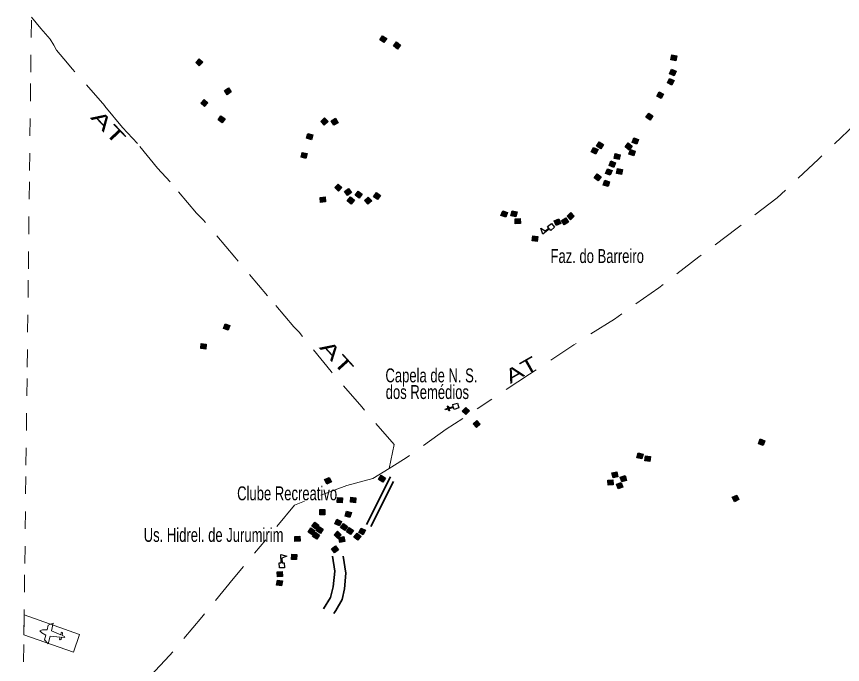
# Model space of a CAD drawing. Extents: x 679 to 705, y 7427.4 to 7455.4.
# Drawn here: x 679.037 to 683.784, y 7431.066 to 7434.793 of the extents above; entities that cross this region are included whole.
import ezdxf
from ezdxf.enums import TextEntityAlignment as Align

# ---------------------------------------------------------------- set-up
doc = ezdxf.new("R2010")
doc.units = 0
doc.header["$LTSCALE"] = 0.032
doc.linetypes.add('DOT_DASHED', pattern=[7.7, 5, -1.2, 0.3, -1.2])
doc.linetypes.add('SHORT_DASHED', pattern=[2.7, 1.5, -1.2])
for name, color, linetype, lineweight in [('18', 7, 'Continuous', 13), ('2', 7, 'Continuous', 25), ('26', 7, 'Continuous', 35), ('4', 7, 'Continuous', 25), ('56', 7, 'DOT_DASHED', 13), ('58', 7, 'SHORT_DASHED', 13), ('6', 7, 'Continuous', 25)]:
    doc.layers.add(name, color=color, linetype=linetype, lineweight=lineweight)
doc.layers.add('61', color=7, linetype='Continuous')

msp = doc.modelspace()

# ---------------------------------------------------------------- hatches: boundary and pattern name
at = {"layer": '2'}
for points in [[(681.1398, 7434.6824), (681.1644, 7434.6671), (681.149, 7434.6425), (681.1244, 7434.6578)], [(681.2217, 7434.6462), (681.2447, 7434.6286), (681.2272, 7434.6056), (681.2041, 7434.6232)], [(682.832, 7434.5663), (682.8263, 7434.5379), (682.7979, 7434.5436), (682.8036, 7434.572)], [(680.0872, 7434.5494), (680.108, 7434.5292), (680.0878, 7434.5084), (680.067, 7434.5286)], [(682.8016, 7434.4889), (682.8283, 7434.4774), (682.8167, 7434.4508), (682.7901, 7434.4623)], [(682.7891, 7434.4369), (682.8157, 7434.4252), (682.8039, 7434.3987), (682.7774, 7434.4104)], [(680.256, 7434.3831), (680.2717, 7434.3588), (680.2473, 7434.3431), (680.2316, 7434.3674)], [(682.7301, 7434.3601), (682.7557, 7434.3464), (682.7419, 7434.3209), (682.7164, 7434.3346)], [(680.116, 7434.316), (680.1375, 7434.2966), (680.1181, 7434.275), (680.0966, 7434.2945)], [(682.6701, 7434.2369), (682.6942, 7434.2207), (682.6781, 7434.1966), (682.654, 7434.2128)], [(680.2117, 7434.2214), (680.2357, 7434.2051), (680.2194, 7434.1812), (680.1954, 7434.1975)], [(680.8077, 7434.2092), (680.8274, 7434.1879), (680.8061, 7434.1682), (680.7864, 7434.1895)], [(680.8712, 7434.2071), (680.8854, 7434.1819), (680.8601, 7434.1676), (680.8459, 7434.1929)], [(680.7399, 7434.1121), (680.7321, 7434.0842), (680.7042, 7434.092), (680.712, 7434.1199)], [(682.5842, 7434.0958), (682.6116, 7434.0861), (682.6018, 7434.0588), (682.5745, 7434.0685)], [(682.3857, 7434.0719), (682.4104, 7434.0567), (682.3952, 7434.032), (682.3705, 7434.0473)], [(682.5521, 7434.0653), (682.5751, 7434.0475), (682.5573, 7434.0246), (682.5344, 7434.0424)], [(680.7073, 7434.0044), (680.7004, 7433.9762), (680.6722, 7433.9831), (680.6791, 7434.0113)], [(682.3792, 7434.0274), (682.3665, 7434.0013), (682.3404, 7434.014), (682.3531, 7434.0401)], [(682.5063, 7433.9979), (682.5003, 7433.9695), (682.472, 7433.9755), (682.4779, 7434.0039)], [(682.5656, 7434.0282), (682.5931, 7434.019), (682.584, 7433.9915), (682.5565, 7434.0007)], [(682.4798, 7433.9514), (682.4691, 7433.9244), (682.4421, 7433.9352), (682.4529, 7433.9621)], [(682.433, 7433.9175), (682.46, 7433.907), (682.4495, 7433.88), (682.4225, 7433.8905)], [(682.5187, 7433.9125), (682.5134, 7433.884), (682.4849, 7433.8893), (682.4902, 7433.9178)], [(682.3732, 7433.8881), (682.3966, 7433.8709), (682.3794, 7433.8475), (682.356, 7433.8647)], [(682.4181, 7433.851), (682.4456, 7433.8418), (682.4364, 7433.8143), (682.4089, 7433.8235)], [(680.8862, 7433.8293), (680.9071, 7433.8093), (680.8871, 7433.7883), (680.8661, 7433.8083)], [(680.9455, 7433.8038), (680.963, 7433.7807), (680.9399, 7433.7632), (680.9224, 7433.7863)], [(680.9998, 7433.7881), (681.0236, 7433.7716), (681.0071, 7433.7478), (680.9833, 7433.7643)], [(681.1051, 7433.7797), (681.129, 7433.7633), (681.1126, 7433.7394), (681.0887, 7433.7558)], [(680.8105, 7433.7547), (680.8132, 7433.7259), (680.7844, 7433.7231), (680.7816, 7433.752)], [(680.9561, 7433.7546), (680.9788, 7433.7366), (680.9607, 7433.7139), (680.938, 7433.7319)], [(681.059, 7433.7534), (681.0785, 7433.7318), (681.057, 7433.7124), (681.0375, 7433.7339)], [(681.8586, 7433.6648), (681.8482, 7433.6377), (681.8212, 7433.6481), (681.8316, 7433.6752)], [(681.9136, 7433.6685), (681.9069, 7433.6403), (681.8787, 7433.647), (681.8854, 7433.6752)], [(682.2222, 7433.6648), (682.242, 7433.6436), (682.2208, 7433.6238), (682.201, 7433.645)], [(681.9312, 7433.6304), (681.9325, 7433.6014), (681.9035, 7433.6001), (681.9022, 7433.6291)], [(682.1545, 7433.6283), (682.1656, 7433.6015), (682.1389, 7433.5904), (682.1277, 7433.6171)], [(682.1937, 7433.6348), (682.209, 7433.6102), (682.1843, 7433.5949), (682.169, 7433.6196)], [(682.0334, 7433.5279), (682.0293, 7433.4992), (682.0006, 7433.5033), (682.0047, 7433.532)], [(680.2631, 7433.0156), (680.2539, 7432.9881), (680.2264, 7432.9973), (680.2356, 7433.0248)], [(680.1278, 7432.9082), (680.1245, 7432.8794), (680.0957, 7432.8826), (680.099, 7432.9114)], [(681.6188, 7432.5439), (681.6397, 7432.5238), (681.6197, 7432.5029), (681.5987, 7432.523)], [(681.6816, 7432.4694), (681.7015, 7432.4483), (681.6804, 7432.4284), (681.6605, 7432.4495)], [(683.3378, 7432.353), (683.3278, 7432.3258), (683.3006, 7432.3358), (683.3106, 7432.363)], [(682.638, 7432.2759), (682.6306, 7432.2478), (682.6026, 7432.2552), (682.61, 7432.2833)], [(682.6798, 7432.2629), (682.6769, 7432.234), (682.6481, 7432.2369), (682.6509, 7432.2658)], [(680.8342, 7432.1422), (680.8465, 7432.1159), (680.8202, 7432.1036), (680.8079, 7432.1299)], [(681.1579, 7432.1379), (681.1419, 7432.1137), (681.1177, 7432.1296), (681.1336, 7432.1538)], [(682.4867, 7432.1742), (682.4932, 7432.1459), (682.465, 7432.1394), (682.4585, 7432.1677)], [(682.5346, 7432.1524), (682.5433, 7432.1248), (682.5156, 7432.1161), (682.5069, 7432.1437)], [(682.4637, 7432.1276), (682.4661, 7432.0987), (682.4372, 7432.0963), (682.4348, 7432.1252)], [(682.5115, 7432.1133), (682.5211, 7432.086), (682.4938, 7432.0764), (682.4842, 7432.1037)], [(680.9113, 7432.0241), (680.9095, 7431.9952), (680.8805, 7431.997), (680.8824, 7432.026)], [(680.9876, 7432.0251), (680.9849, 7431.9962), (680.956, 7431.9989), (680.9587, 7432.0278)], [(683.1766, 7432.0406), (683.1888, 7432.0143), (683.1625, 7432.0021), (683.1503, 7432.0284)], [(680.7797, 7431.9563), (680.8087, 7431.9563), (680.8087, 7431.9273), (680.7797, 7431.9273)], [(680.9615, 7431.9392), (680.9536, 7431.9113), (680.9257, 7431.9193), (680.9337, 7431.9472)], [(680.7522, 7431.884), (680.7752, 7431.8665), (680.7577, 7431.8434), (680.7346, 7431.861)], [(680.7763, 7431.8599), (680.8004, 7431.8438), (680.7843, 7431.8197), (680.7602, 7431.8358)], [(680.9052, 7431.8888), (680.8932, 7431.8624), (680.8668, 7431.8744), (680.8788, 7431.9008)], [(680.9399, 7431.8602), (680.9234, 7431.8363), (680.8995, 7431.8528), (680.916, 7431.8767)], [(680.728, 7431.8514), (680.7525, 7431.8359), (680.7371, 7431.8114), (680.7125, 7431.8268)], [(680.7552, 7431.8262), (680.7793, 7431.8101), (680.7632, 7431.786), (680.7391, 7431.8021)], [(680.9037, 7431.8124), (680.8839, 7431.7912), (680.8627, 7431.8109), (680.8824, 7431.8322)], [(680.9497, 7431.853), (680.9733, 7431.8362), (680.9564, 7431.8126), (680.9328, 7431.8294)], [(681.0173, 7431.8028), (680.9994, 7431.78), (680.9766, 7431.7979), (680.9946, 7431.8207)], [(681.0431, 7431.8375), (681.0302, 7431.8116), (681.0042, 7431.8246), (681.0172, 7431.8505)], [(680.6655, 7431.8033), (680.6665, 7431.7743), (680.6375, 7431.7733), (680.6365, 7431.8023)], [(680.9188, 7431.801), (680.9243, 7431.7725), (680.8959, 7431.767), (680.8903, 7431.7954)], [(680.8699, 7431.7491), (680.8873, 7431.7259), (680.8641, 7431.7085), (680.8467, 7431.7317)], [(680.6483, 7431.6982), (680.647, 7431.6692), (680.618, 7431.6705), (680.6193, 7431.6995)], [(680.5641, 7431.6011), (680.5655, 7431.5721), (680.5366, 7431.5706), (680.5351, 7431.5996)], [(680.5655, 7431.546), (680.5607, 7431.5174), (680.5321, 7431.5221), (680.5369, 7431.5507)]]:
    msp.add_hatch(color=256, dxfattribs=at).paths.add_polyline_path(points)

# ---------------------------------------------------------------- linework, layer by layer
at = {"layer": '18'}
for points in [[(679.0801, 7431.236), (679.0814, 7431.3513), (679.3998, 7431.2391), (679.3656, 7431.1374)], [(679.1712, 7431.2599), (679.1874, 7431.2644), (679.2134, 7431.266), (679.2201, 7431.2924), (679.2487, 7431.3044), (679.2377, 7431.2598), (679.2914, 7431.2371), (679.2942, 7431.2487), (679.2993, 7431.2515), (679.3023, 7431.2466), (679.299, 7431.2334), (679.3122, 7431.2275), (679.3156, 7431.2235), (679.3107, 7431.2214), (679.2964, 7431.2228), (679.2933, 7431.2097), (679.2881, 7431.2067), (679.2851, 7431.2118), (679.2877, 7431.2229), (679.2298, 7431.2285), (679.2186, 7431.184), (679.1989, 7431.208), (679.2056, 7431.2345), (679.1833, 7431.2482)]]:
    msp.add_lwpolyline(points, close=True, dxfattribs=at)
at = {"layer": '2'}
for points in [[(681.1398, 7434.6824), (681.1644, 7434.6671), (681.149, 7434.6425), (681.1244, 7434.6578)], [(681.2217, 7434.6462), (681.2447, 7434.6286), (681.2272, 7434.6056), (681.2041, 7434.6232)], [(682.832, 7434.5663), (682.8263, 7434.5379), (682.7979, 7434.5436), (682.8036, 7434.572)], [(680.0872, 7434.5494), (680.108, 7434.5292), (680.0878, 7434.5084), (680.067, 7434.5286)], [(682.8016, 7434.4889), (682.8283, 7434.4774), (682.8167, 7434.4508), (682.7901, 7434.4623)], [(682.7891, 7434.4369), (682.8157, 7434.4252), (682.8039, 7434.3987), (682.7774, 7434.4104)], [(680.256, 7434.3831), (680.2717, 7434.3588), (680.2473, 7434.3431), (680.2316, 7434.3674)], [(682.7301, 7434.3601), (682.7557, 7434.3464), (682.7419, 7434.3209), (682.7164, 7434.3346)], [(680.116, 7434.316), (680.1375, 7434.2966), (680.1181, 7434.275), (680.0966, 7434.2945)], [(682.6701, 7434.2369), (682.6942, 7434.2207), (682.6781, 7434.1966), (682.654, 7434.2128)], [(680.2117, 7434.2214), (680.2357, 7434.2051), (680.2194, 7434.1812), (680.1954, 7434.1975)], [(680.8077, 7434.2092), (680.8274, 7434.1879), (680.8061, 7434.1682), (680.7864, 7434.1895)], [(680.8712, 7434.2071), (680.8854, 7434.1819), (680.8601, 7434.1676), (680.8459, 7434.1929)], [(680.7399, 7434.1121), (680.7321, 7434.0842), (680.7042, 7434.092), (680.712, 7434.1199)], [(682.5842, 7434.0958), (682.6116, 7434.0861), (682.6018, 7434.0588), (682.5745, 7434.0685)], [(682.3857, 7434.0719), (682.4104, 7434.0567), (682.3952, 7434.032), (682.3705, 7434.0473)], [(682.5521, 7434.0653), (682.5751, 7434.0475), (682.5573, 7434.0246), (682.5344, 7434.0424)], [(680.7073, 7434.0044), (680.7004, 7433.9762), (680.6722, 7433.9831), (680.6791, 7434.0113)], [(682.3792, 7434.0274), (682.3665, 7434.0013), (682.3404, 7434.014), (682.3531, 7434.0401)], [(682.5063, 7433.9979), (682.5003, 7433.9695), (682.472, 7433.9755), (682.4779, 7434.0039)], [(682.5656, 7434.0282), (682.5931, 7434.019), (682.584, 7433.9915), (682.5565, 7434.0007)], [(682.4798, 7433.9514), (682.4691, 7433.9244), (682.4421, 7433.9352), (682.4529, 7433.9621)], [(682.433, 7433.9175), (682.46, 7433.907), (682.4495, 7433.88), (682.4225, 7433.8905)], [(682.5187, 7433.9125), (682.5134, 7433.884), (682.4849, 7433.8893), (682.4902, 7433.9178)], [(682.3732, 7433.8881), (682.3966, 7433.8709), (682.3794, 7433.8475), (682.356, 7433.8647)], [(682.4181, 7433.851), (682.4456, 7433.8418), (682.4364, 7433.8143), (682.4089, 7433.8235)], [(680.8862, 7433.8293), (680.9071, 7433.8093), (680.8871, 7433.7883), (680.8661, 7433.8083)], [(680.9455, 7433.8038), (680.963, 7433.7807), (680.9399, 7433.7632), (680.9224, 7433.7863)], [(680.9998, 7433.7881), (681.0236, 7433.7716), (681.0071, 7433.7478), (680.9833, 7433.7643)], [(681.1051, 7433.7797), (681.129, 7433.7633), (681.1126, 7433.7394), (681.0887, 7433.7558)], [(680.8105, 7433.7547), (680.8132, 7433.7259), (680.7844, 7433.7231), (680.7816, 7433.752)], [(680.9561, 7433.7546), (680.9788, 7433.7366), (680.9607, 7433.7139), (680.938, 7433.7319)], [(681.059, 7433.7534), (681.0785, 7433.7318), (681.057, 7433.7124), (681.0375, 7433.7339)], [(681.8586, 7433.6648), (681.8482, 7433.6377), (681.8212, 7433.6481), (681.8316, 7433.6752)], [(681.9136, 7433.6685), (681.9069, 7433.6403), (681.8787, 7433.647), (681.8854, 7433.6752)], [(682.2222, 7433.6648), (682.242, 7433.6436), (682.2208, 7433.6238), (682.201, 7433.645)], [(681.9312, 7433.6304), (681.9325, 7433.6014), (681.9035, 7433.6001), (681.9022, 7433.6291)], [(682.1545, 7433.6283), (682.1656, 7433.6015), (682.1389, 7433.5904), (682.1277, 7433.6171)], [(682.1937, 7433.6348), (682.209, 7433.6102), (682.1843, 7433.5949), (682.169, 7433.6196)], [(682.0334, 7433.5279), (682.0293, 7433.4992), (682.0006, 7433.5033), (682.0047, 7433.532)], [(680.2631, 7433.0156), (680.2539, 7432.9881), (680.2264, 7432.9973), (680.2356, 7433.0248)], [(680.1278, 7432.9082), (680.1245, 7432.8794), (680.0957, 7432.8826), (680.099, 7432.9114)], [(681.6188, 7432.5439), (681.6397, 7432.5238), (681.6197, 7432.5029), (681.5987, 7432.523)], [(681.6816, 7432.4694), (681.7015, 7432.4483), (681.6804, 7432.4284), (681.6605, 7432.4495)], [(683.3378, 7432.353), (683.3278, 7432.3258), (683.3006, 7432.3358), (683.3106, 7432.363)], [(682.638, 7432.2759), (682.6306, 7432.2478), (682.6026, 7432.2552), (682.61, 7432.2833)], [(682.6798, 7432.2629), (682.6769, 7432.234), (682.6481, 7432.2369), (682.6509, 7432.2658)], [(680.8342, 7432.1422), (680.8465, 7432.1159), (680.8202, 7432.1036), (680.8079, 7432.1299)], [(681.1579, 7432.1379), (681.1419, 7432.1137), (681.1177, 7432.1296), (681.1336, 7432.1538)], [(682.4867, 7432.1742), (682.4932, 7432.1459), (682.465, 7432.1394), (682.4585, 7432.1677)], [(682.5346, 7432.1524), (682.5433, 7432.1248), (682.5156, 7432.1161), (682.5069, 7432.1437)], [(682.4637, 7432.1276), (682.4661, 7432.0987), (682.4372, 7432.0963), (682.4348, 7432.1252)], [(682.5115, 7432.1133), (682.5211, 7432.086), (682.4938, 7432.0764), (682.4842, 7432.1037)], [(680.9113, 7432.0241), (680.9095, 7431.9952), (680.8805, 7431.997), (680.8824, 7432.026)], [(680.9876, 7432.0251), (680.9849, 7431.9962), (680.956, 7431.9989), (680.9587, 7432.0278)], [(683.1766, 7432.0406), (683.1888, 7432.0143), (683.1625, 7432.0021), (683.1503, 7432.0284)], [(680.7797, 7431.9563), (680.8087, 7431.9563), (680.8087, 7431.9273), (680.7797, 7431.9273)], [(680.9615, 7431.9392), (680.9536, 7431.9113), (680.9257, 7431.9193), (680.9337, 7431.9472)], [(680.7522, 7431.884), (680.7752, 7431.8665), (680.7577, 7431.8434), (680.7346, 7431.861)], [(680.7763, 7431.8599), (680.8004, 7431.8438), (680.7843, 7431.8197), (680.7602, 7431.8358)], [(680.9052, 7431.8888), (680.8932, 7431.8624), (680.8668, 7431.8744), (680.8788, 7431.9008)], [(680.9399, 7431.8602), (680.9234, 7431.8363), (680.8995, 7431.8528), (680.916, 7431.8767)], [(680.728, 7431.8514), (680.7525, 7431.8359), (680.7371, 7431.8114), (680.7125, 7431.8268)], [(680.7552, 7431.8262), (680.7793, 7431.8101), (680.7632, 7431.786), (680.7391, 7431.8021)], [(680.9037, 7431.8124), (680.8839, 7431.7912), (680.8627, 7431.8109), (680.8824, 7431.8322)], [(680.9497, 7431.853), (680.9733, 7431.8362), (680.9564, 7431.8126), (680.9328, 7431.8294)], [(681.0173, 7431.8028), (680.9994, 7431.78), (680.9766, 7431.7979), (680.9946, 7431.8207)], [(681.0431, 7431.8375), (681.0302, 7431.8116), (681.0042, 7431.8246), (681.0172, 7431.8505)], [(680.6655, 7431.8033), (680.6665, 7431.7743), (680.6375, 7431.7733), (680.6365, 7431.8023)], [(680.9188, 7431.801), (680.9243, 7431.7725), (680.8959, 7431.767), (680.8903, 7431.7954)], [(680.8699, 7431.7491), (680.8873, 7431.7259), (680.8641, 7431.7085), (680.8467, 7431.7317)], [(680.6483, 7431.6982), (680.647, 7431.6692), (680.618, 7431.6705), (680.6193, 7431.6995)], [(680.5641, 7431.6011), (680.5655, 7431.5721), (680.5366, 7431.5706), (680.5351, 7431.5996)], [(680.5655, 7431.546), (680.5607, 7431.5174), (680.5321, 7431.5221), (680.5369, 7431.5507)]]:
    msp.add_lwpolyline(points, close=True, dxfattribs=at)
at = {"layer": '26'}
for p, q in [((681.1871, 7432.1452), (681.0491, 7431.8702)), ((681.0731, 7431.859), (681.2038, 7432.118)), ((680.8604, 7431.3591), (680.8732, 7431.376))]:
    msp.add_line(p, q, dxfattribs=at)
for points in [[(680.8005, 7431.3852), (680.8416, 7431.4517), (680.8579, 7431.5128), (680.8665, 7431.6028), (680.8539, 7431.6883)], [(680.8732, 7431.376), (680.9078, 7431.4391), (680.9212, 7431.5004), (680.9298, 7431.5904), (680.9153, 7431.6894)]]:
    msp.add_lwpolyline(points, dxfattribs=at)
at = {"layer": '4'}
for points in [[(682.0996, 7433.5717), (682.0617, 7433.5416), (682.0497, 7433.5754), (682.0761, 7433.5593), (682.0965, 7433.5756)], [(682.0965, 7433.5756), (682.089, 7433.5851), (682.1117, 7433.6031), (682.1297, 7433.5804), (682.107, 7433.5624), (682.0996, 7433.5717)], [(680.5587, 7431.6505), (680.5569, 7431.6989), (680.5912, 7431.6886), (680.5626, 7431.6768), (680.5635, 7431.6507)], [(680.5635, 7431.6507), (680.5756, 7431.6512), (680.5767, 7431.6222), (680.5477, 7431.6211), (680.5467, 7431.6501), (680.5587, 7431.6505)]]:
    msp.add_lwpolyline(points, dxfattribs=at)
at = {"layer": '56'}
msp.add_line((681.225, 7432.2223), (681.1789, 7432.1929), dxfattribs=at)
for points in [[(681.1789, 7432.1929), (681.2066, 7432.3309), (681.0222, 7432.5471), (680.8446, 7432.7506), (680.6623, 7432.9765), (680.6305, 7433.0083), (680.4793, 7433.1859), (680.2913, 7433.4087), (680.1099, 7433.6237), (680.072, 7433.662), (679.9201, 7433.8416), (679.8474, 7433.9208), (679.7332, 7434.0623), (679.6461, 7434.1535), (679.5441, 7434.2788), (679.3594, 7434.4904), (679.3098, 7434.549), (679.2672, 7434.5989), (679.2523, 7434.6279), (679.2306, 7434.6632), (679.1772, 7434.7246), (679.1228, 7434.7885)], [(683.8542, 7434.1713), (683.6453, 7433.9724), (683.4081, 7433.749), (683.1791, 7433.5757), (682.9584, 7433.4101), (682.7275, 7433.2325), (682.4732, 7433.0527), (682.2404, 7432.9041), (681.985, 7432.7355), (681.507, 7432.4183), (681.2818, 7432.2585), (681.225, 7432.2223)], [(681.1789, 7432.1929), (681.0842, 7432.1347), (680.9359, 7432.0959), (680.6351, 7431.9829), (680.2832, 7431.5576), (680.1018, 7431.3382), (679.9169, 7431.1174), (679.7096, 7430.8935)]]:
    msp.add_lwpolyline(points, dxfattribs=at)
at = {"layer": '58'}
msp.add_lwpolyline([(679.0374, 7427.6915), (679.0442, 7428.2565), (679.051, 7428.8215), (679.0578, 7429.3865), (679.0646, 7429.9515), (679.0714, 7430.5166), (679.0782, 7431.0816), (679.085, 7431.6466), (679.0918, 7432.2116), (679.0986, 7432.7766), (679.1054, 7433.3416), (679.1122, 7433.9066), (679.119, 7434.4716), (679.1258, 7435.0366), (679.1326, 7435.6016), (679.1394, 7436.1666), (679.1462, 7436.7316), (679.153, 7437.2966), (679.1598, 7437.8616), (679.1666, 7438.4266), (679.1734, 7438.9916), (679.1802, 7439.5566), (679.1869, 7440.1216)], dxfattribs=at)
at = {"layer": '6'}
for points in [[(681.5473, 7432.5494), (681.5437, 7432.5609), (681.5714, 7432.5695), (681.58, 7432.5418), (681.5523, 7432.5332), (681.5487, 7432.5448)], [(681.5487, 7432.5448), (681.5228, 7432.5368), (681.5264, 7432.5252), (681.5217, 7432.5238), (681.5181, 7432.5354), (681.5025, 7432.5305), (681.5011, 7432.5351), (681.5167, 7432.5399), (681.5132, 7432.5515), (681.5178, 7432.5529), (681.5214, 7432.5414), (681.5473, 7432.5494)]]:
    msp.add_lwpolyline(points, dxfattribs=at)

# ---------------------------------------------------------------- texts
at = {"layer": '61'}
for rotation, width, p in [(313.598, 1.65, (679.5359, 7434.128)), (312.228, 1.6, (680.8477, 7432.8065)), (29.539, 1.4, (681.9576, 7432.7255))]:
    msp.add_text('AT', height=0.08, rotation=rotation, dxfattribs=dict(at, width=width)).set_placement(p, align=Align.CENTER)
at = {"layer": '61', "width": 0.7}
for s, p in [('Faz. do Barreiro', (682.1058, 7433.3749)), ('Capela de N. S. ', (681.1574, 7432.6885)), ('dos Remédios', (681.1589, 7432.5927)), ('Clube Recreativo', (680.3052, 7432.0101)), ('Us. Hidrel. de Jurumirim', (679.7683, 7431.7711))]:
    msp.add_text(s, height=0.08, dxfattribs=at).set_placement(p)

doc.saveas('drawing.dxf')
